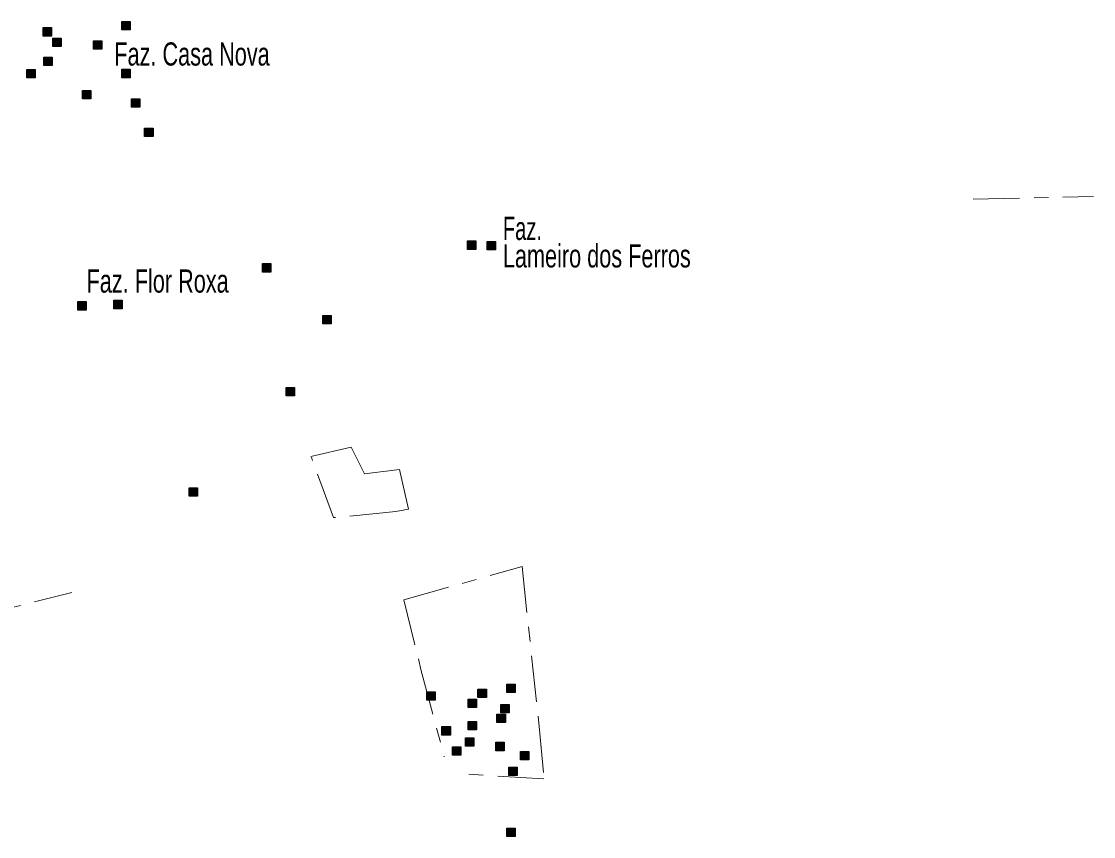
# Model space of a CAD drawing. Extents: x 445.4 to 500, y 8728.7 to 8784.
# Drawn here: x 472.09 to 479.49, y 8746.37 to 8752.01 of the extents above; entities that cross this region are included whole.
import ezdxf

# ---------------------------------------------------------------- set-up
doc = ezdxf.new("R2010")
doc.units = 0
doc.header["$LTSCALE"] = 0.064
doc.linetypes.add('DOT_DASHED', pattern=[7.7, 5, -1.2, 0.3, -1.2])
doc.layers.add('2', color=7, linetype='Continuous', lineweight=25)
doc.layers.add('22', color=7, linetype='DOT_DASHED', lineweight=13)
doc.layers.add('61', color=7, linetype='Continuous')

msp = doc.modelspace()

# ---------------------------------------------------------------- hatches: boundary and pattern name
at = {"layer": '2'}
for points in [[(472.7795, 8752.0063), (472.8375, 8752.0063), (472.8375, 8751.9483), (472.7795, 8751.9483)], [(472.2365, 8751.9636), (472.2945, 8751.9636), (472.2945, 8751.9056), (472.2365, 8751.9056)], [(472.3043, 8751.8912), (472.3623, 8751.8912), (472.3623, 8751.8332), (472.3043, 8751.8332)], [(472.5849, 8751.8731), (472.6429, 8751.8731), (472.6429, 8751.8151), (472.5849, 8751.8151)], [(472.241, 8751.7599), (472.299, 8751.7599), (472.299, 8751.7019), (472.241, 8751.7019)], [(472.1233, 8751.6739), (472.1813, 8751.6739), (472.1813, 8751.6159), (472.1233, 8751.6159)], [(472.7795, 8751.6758), (472.8375, 8751.6758), (472.8375, 8751.6178), (472.7795, 8751.6178)], [(472.508, 8751.529), (472.566, 8751.529), (472.566, 8751.471), (472.508, 8751.471)], [(472.8474, 8751.4721), (472.9054, 8751.4721), (472.9054, 8751.4141), (472.8474, 8751.4141)], [(472.9379, 8751.2684), (472.9959, 8751.2684), (472.9959, 8751.2104), (472.9379, 8751.2104)], [(475.1687, 8750.4896), (475.2267, 8750.4896), (475.2267, 8750.4316), (475.1687, 8750.4316)], [(475.3045, 8750.4851), (475.3625, 8750.4851), (475.3625, 8750.4271), (475.3045, 8750.4271)], [(473.7524, 8750.3329), (473.8104, 8750.3329), (473.8104, 8750.2749), (473.7524, 8750.2749)], [(472.7252, 8750.0794), (472.7832, 8750.0794), (472.7832, 8750.0214), (472.7252, 8750.0214)], [(472.4763, 8750.0704), (472.5343, 8750.0704), (472.5343, 8750.0124), (472.4763, 8750.0124)], [(474.1687, 8749.9753), (474.2267, 8749.9753), (474.2267, 8749.9173), (474.1687, 8749.9173)], [(473.9153, 8749.4773), (473.9733, 8749.4773), (473.9733, 8749.4193), (473.9153, 8749.4193)], [(473.2456, 8748.7846), (473.3036, 8748.7846), (473.3036, 8748.7266), (473.2456, 8748.7266)], [(475.4402, 8747.4281), (475.4982, 8747.4281), (475.4982, 8747.3701), (475.4402, 8747.3701)], [(474.8882, 8747.3738), (474.9462, 8747.3738), (474.9462, 8747.3158), (474.8882, 8747.3158)], [(475.2411, 8747.3919), (475.2991, 8747.3919), (475.2991, 8747.3339), (475.2411, 8747.3339)], [(475.1732, 8747.324), (475.2312, 8747.324), (475.2312, 8747.266), (475.1732, 8747.266)], [(475.3995, 8747.2877), (475.4575, 8747.2877), (475.4575, 8747.2297), (475.3995, 8747.2297)], [(475.3723, 8747.2198), (475.4303, 8747.2198), (475.4303, 8747.1618), (475.3723, 8747.1618)], [(474.9922, 8747.1338), (475.0502, 8747.1338), (475.0502, 8747.0758), (474.9922, 8747.0758)], [(475.1732, 8747.17), (475.2312, 8747.17), (475.2312, 8747.112), (475.1732, 8747.112)], [(475.1551, 8747.0568), (475.2131, 8747.0568), (475.2131, 8746.9988), (475.1551, 8746.9988)], [(475.0646, 8746.9935), (475.1226, 8746.9935), (475.1226, 8746.9355), (475.0646, 8746.9355)], [(475.3633, 8747.0252), (475.4213, 8747.0252), (475.4213, 8746.9672), (475.3633, 8746.9672)], [(475.5352, 8746.9618), (475.5932, 8746.9618), (475.5932, 8746.9038), (475.5352, 8746.9038)], [(475.4538, 8746.8531), (475.5118, 8746.8531), (475.5118, 8746.7951), (475.4538, 8746.7951)], [(475.4402, 8746.4321), (475.4982, 8746.4321), (475.4982, 8746.3741), (475.4402, 8746.3741)]]:
    msp.add_hatch(color=256, dxfattribs=at).paths.add_polyline_path(points)

# ---------------------------------------------------------------- linework, layer by layer
for points in [[(472.7795, 8752.0063), (472.8375, 8752.0063), (472.8375, 8751.9483), (472.7795, 8751.9483)], [(472.2365, 8751.9636), (472.2945, 8751.9636), (472.2945, 8751.9056), (472.2365, 8751.9056)], [(472.3043, 8751.8912), (472.3623, 8751.8912), (472.3623, 8751.8332), (472.3043, 8751.8332)], [(472.5849, 8751.8731), (472.6429, 8751.8731), (472.6429, 8751.8151), (472.5849, 8751.8151)], [(472.241, 8751.7599), (472.299, 8751.7599), (472.299, 8751.7019), (472.241, 8751.7019)], [(472.1233, 8751.6739), (472.1813, 8751.6739), (472.1813, 8751.6159), (472.1233, 8751.6159)], [(472.7795, 8751.6758), (472.8375, 8751.6758), (472.8375, 8751.6178), (472.7795, 8751.6178)], [(472.508, 8751.529), (472.566, 8751.529), (472.566, 8751.471), (472.508, 8751.471)], [(472.8474, 8751.4721), (472.9054, 8751.4721), (472.9054, 8751.4141), (472.8474, 8751.4141)], [(472.9379, 8751.2684), (472.9959, 8751.2684), (472.9959, 8751.2104), (472.9379, 8751.2104)], [(475.1687, 8750.4896), (475.2267, 8750.4896), (475.2267, 8750.4316), (475.1687, 8750.4316)], [(475.3045, 8750.4851), (475.3625, 8750.4851), (475.3625, 8750.4271), (475.3045, 8750.4271)], [(473.7524, 8750.3329), (473.8104, 8750.3329), (473.8104, 8750.2749), (473.7524, 8750.2749)], [(472.7252, 8750.0794), (472.7832, 8750.0794), (472.7832, 8750.0214), (472.7252, 8750.0214)], [(472.4763, 8750.0704), (472.5343, 8750.0704), (472.5343, 8750.0124), (472.4763, 8750.0124)], [(474.1687, 8749.9753), (474.2267, 8749.9753), (474.2267, 8749.9173), (474.1687, 8749.9173)], [(473.9153, 8749.4773), (473.9733, 8749.4773), (473.9733, 8749.4193), (473.9153, 8749.4193)], [(473.2456, 8748.7846), (473.3036, 8748.7846), (473.3036, 8748.7266), (473.2456, 8748.7266)], [(475.4402, 8747.4281), (475.4982, 8747.4281), (475.4982, 8747.3701), (475.4402, 8747.3701)], [(474.8882, 8747.3738), (474.9462, 8747.3738), (474.9462, 8747.3158), (474.8882, 8747.3158)], [(475.2411, 8747.3919), (475.2991, 8747.3919), (475.2991, 8747.3339), (475.2411, 8747.3339)], [(475.1732, 8747.324), (475.2312, 8747.324), (475.2312, 8747.266), (475.1732, 8747.266)], [(475.3995, 8747.2877), (475.4575, 8747.2877), (475.4575, 8747.2297), (475.3995, 8747.2297)], [(475.3723, 8747.2198), (475.4303, 8747.2198), (475.4303, 8747.1618), (475.3723, 8747.1618)], [(474.9922, 8747.1338), (475.0502, 8747.1338), (475.0502, 8747.0758), (474.9922, 8747.0758)], [(475.1732, 8747.17), (475.2312, 8747.17), (475.2312, 8747.112), (475.1732, 8747.112)], [(475.1551, 8747.0568), (475.2131, 8747.0568), (475.2131, 8746.9988), (475.1551, 8746.9988)], [(475.0646, 8746.9935), (475.1226, 8746.9935), (475.1226, 8746.9355), (475.0646, 8746.9355)], [(475.3633, 8747.0252), (475.4213, 8747.0252), (475.4213, 8746.9672), (475.3633, 8746.9672)], [(475.5352, 8746.9618), (475.5932, 8746.9618), (475.5932, 8746.9038), (475.5352, 8746.9038)], [(475.4538, 8746.8531), (475.5118, 8746.8531), (475.5118, 8746.7951), (475.4538, 8746.7951)], [(475.4402, 8746.4321), (475.4982, 8746.4321), (475.4982, 8746.3741), (475.4402, 8746.3741)]]:
    msp.add_lwpolyline(points, close=True, dxfattribs=at)
at = {"layer": '22'}
msp.add_line((478.6632, 8750.7779), (479.4943, 8750.7969), dxfattribs=at)
for points in [[(474.0864, 8749.0003), (474.364, 8749.0648), (474.4571, 8748.8803), (474.6982, 8748.9103), (474.7616, 8748.6352), (474.6744, 8748.6194), (474.2425, 8748.5779), (474.0978, 8748.9736), (474.0899, 8748.9954)], [(474.7286, 8748.0094), (475.5456, 8748.2397), (475.6642, 8747.1343), (475.6971, 8746.7724), (475.1463, 8746.8067)], [(470.1774, 8747.5197), (470.9289, 8747.7017), (471.5746, 8747.8464), (472.4349, 8748.0596)], [(474.7286, 8748.0094), (474.8472, 8747.5291), (475.008, 8746.9259)]]:
    msp.add_lwpolyline(points, dxfattribs=at)

# ---------------------------------------------------------------- texts
at = {"layer": '61'}
for s, width, p in [('Faz. Casa Nova', 0.7, (472.7283, 8751.7015)), ('Faz.', 0.65, (475.4129, 8750.4964)), ('Lameiro dos Ferros', 0.7, (475.4129, 8750.3064)), (' Faz. Flor Roxa', 0.7, (472.495, 8750.1326))]:
    msp.add_text(s, height=0.16, dxfattribs=dict(at, width=width)).set_placement(p)

doc.saveas('drawing.dxf')
